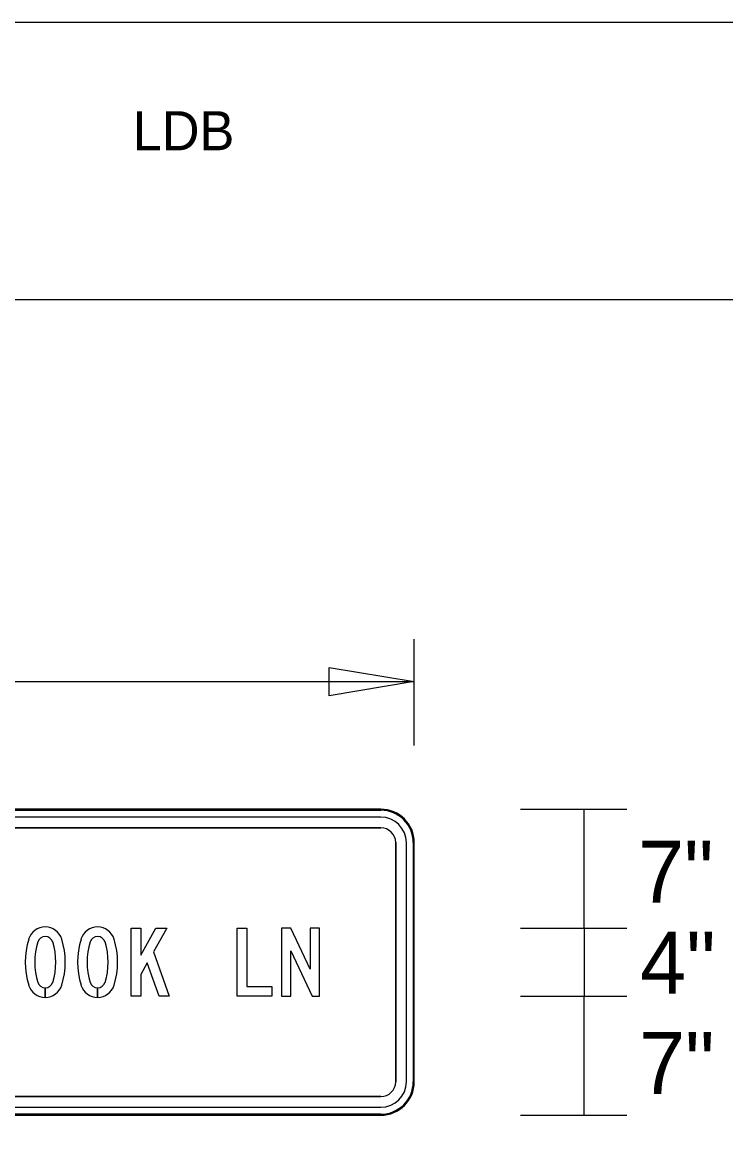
# Model space of a CAD drawing. Extents: x 766449 to 768137, y 650958 to 652521.
# Drawn here: x 767869.7 to 767957.4, y 652115.6 to 652254.2 of the extents above; entities that cross this region are included whole.
import ezdxf

# ---------------------------------------------------------------- set-up
doc = ezdxf.new("R2010")
doc.units = 0
doc.layers.add('Default', color=7, linetype='Continuous')
doc.layers.add('Text', color=7, linetype='Continuous')

msp = doc.modelspace()

# ---------------------------------------------------------------- linework, layer by layer
at = {"layer": 'Default'}
for p, q in [((767918.56, 652164.2), (767918.56, 652177.43)), ((767804.24, 652172.14), (767918.56, 652172.14)), ((767918.56, 652164.2), (767918.56, 652164.2)), ((767914.39, 652156.26), (767808.41, 652156.26)), ((767914.39, 652156.26), (767808.41, 652156.26)), ((767914.39, 652156.26), (767808.41, 652156.26)), ((767914.39, 652156.26), (767808.41, 652156.26)), ((767808.41, 652156.13), (767914.39, 652156.13)), ((767931.79, 652156.26), (767945.02, 652156.26)), ((767931.79, 652156.26), (767931.79, 652156.26)), ((767939.73, 652141.44), (767939.73, 652156.26)), ((767914.39, 652155.27), (767808.41, 652155.27)), ((767914.39, 652155.27), (767808.41, 652155.27)), ((767914.39, 652155.27), (767808.41, 652155.27)), ((767914.39, 652153.95), (767808.41, 652153.95)), ((767808.41, 652153.95), (767914.39, 652153.95)), ((767808.41, 652153.95), (767914.39, 652153.95)), ((767916.24, 652122.32), (767916.24, 652152.09)), ((767916.24, 652152.09), (767916.24, 652122.32)), ((767916.24, 652152.09), (767916.24, 652122.32)), ((767917.57, 652122.32), (767917.57, 652152.09)), ((767917.57, 652122.32), (767917.57, 652152.09)), ((767917.57, 652122.32), (767917.57, 652152.09)), ((767918.43, 652152.09), (767918.43, 652122.32)), ((767918.56, 652122.32), (767918.56, 652152.09)), ((767918.56, 652122.32), (767918.56, 652152.09)), ((767918.56, 652122.32), (767918.56, 652152.09)), ((767918.56, 652122.32), (767918.56, 652152.09)), ((767931.79, 652141.44), (767945.02, 652141.44)), ((767931.79, 652141.44), (767945.02, 652141.44)), ((767939.73, 652141.44), (767939.73, 652132.98)), ((767872.58, 652134.01), (767872.58, 652132.83)), ((767872.58, 652132.83), (767872.58, 652134.01)), ((767872.58, 652134.01), (767872.58, 652132.83)), ((767872.58, 652132.83), (767872.58, 652134.01)), ((767879.1, 652134.01), (767879.1, 652132.83)), ((767879.1, 652132.83), (767879.1, 652134.01)), ((767879.1, 652134.01), (767879.1, 652132.83)), ((767879.1, 652132.83), (767879.1, 652134.01)), ((767931.79, 652132.98), (767945.02, 652132.98)), ((767931.79, 652132.98), (767945.02, 652132.98)), ((767939.73, 652118.16), (767939.73, 652132.98)), ((767808.41, 652120.47), (767914.39, 652120.47)), ((767914.39, 652120.47), (767808.42, 652120.47)), ((767914.39, 652120.47), (767808.42, 652120.47)), ((767808.41, 652119.15), (767914.39, 652119.15)), ((767914.39, 652118.29), (767808.41, 652118.29)), ((767808.41, 652118.16), (767914.39, 652118.16)), ((767808.41, 652118.16), (767914.39, 652118.16)), ((767808.41, 652118.16), (767914.39, 652118.16)), ((767808.41, 652118.16), (767914.39, 652118.16)), ((767808.42, 652119.15), (767914.39, 652119.15)), ((767808.42, 652119.15), (767914.39, 652119.15)), ((767931.79, 652118.16), (767945.02, 652118.16)), ((767931.79, 652118.16), (767931.79, 652118.16))]:
    msp.add_line(p, q, dxfattribs=at)
for points in [[(767918.56, 652172.14), (767907.97, 652170.38), (767907.97, 652173.91)], [(767885.29, 652137.12), (767884.48, 652135.69), (767884.48, 652132.98), (767883.3, 652132.98), (767883.3, 652141.44), (767884.48, 652141.44), (767884.48, 652138.09), (767886.38, 652141.44), (767887.74, 652141.44), (767886.06, 652138.48), (767888.04, 652132.98), (767886.78, 652132.98)], [(767885.29, 652137.12), (767884.48, 652135.69), (767884.48, 652132.98), (767883.3, 652132.98), (767883.3, 652141.44), (767884.48, 652141.44), (767884.48, 652138.09), (767886.38, 652141.44), (767887.74, 652141.44), (767886.06, 652138.48), (767888.04, 652132.98), (767886.78, 652132.98)], [(767885.29, 652137.12), (767884.48, 652135.69), (767884.48, 652132.98), (767883.3, 652132.98), (767883.3, 652141.44), (767884.48, 652141.44), (767884.48, 652138.09), (767886.38, 652141.44), (767887.74, 652141.44), (767886.06, 652138.48), (767888.04, 652132.98), (767886.78, 652132.98)], [(767896.51, 652141.44), (767897.69, 652141.44), (767897.69, 652134.16), (767900.83, 652134.16), (767900.83, 652132.98), (767896.51, 652132.98)], [(767896.51, 652141.44), (767897.69, 652141.44), (767897.69, 652134.16), (767900.83, 652134.16), (767900.83, 652132.98), (767896.51, 652132.98)], [(767896.51, 652141.44), (767897.69, 652141.44), (767897.69, 652134.16), (767900.83, 652134.16), (767900.83, 652132.98), (767896.51, 652132.98)], [(767905.82, 652132.98), (767906.75, 652132.98), (767906.75, 652141.44), (767905.57, 652141.44), (767905.57, 652136.33), (767903.18, 652141.44), (767902.01, 652141.44), (767902.01, 652132.98), (767903.2, 652132.98), (767903.2, 652138.61)], [(767905.82, 652132.98), (767906.75, 652132.98), (767906.75, 652141.44), (767905.57, 652141.44), (767905.57, 652136.33), (767903.18, 652141.44), (767902.01, 652141.44), (767902.01, 652132.98), (767903.2, 652132.98), (767903.2, 652138.61)], [(767905.82, 652132.98), (767906.75, 652132.98), (767906.75, 652141.44), (767905.57, 652141.44), (767905.57, 652136.33), (767903.18, 652141.44), (767902.01, 652141.44), (767902.01, 652132.98), (767903.2, 652132.98), (767903.2, 652138.61)]]:
    msp.add_lwpolyline(points, close=True, dxfattribs=at)
for centre, radius, start, end in [((767914.39, 652152.09), 4.17, 0, 90), ((767914.39, 652152.09), 4.17, 0, 90), ((767914.39, 652152.09), 4.17, 0, 90), ((767914.39, 652152.09), 4.17, 0, 90), ((767914.39, 652152.09), 4.04, 0, 90), ((767914.39, 652152.09), 3.18, 0, 90), ((767914.39, 652152.09), 3.18, 0, 90), ((767914.39, 652152.09), 3.18, 0, 90), ((767914.39, 652152.09), 1.85, 0, 90), ((767914.39, 652152.09), 1.85, 0, 90), ((767914.39, 652152.09), 1.85, 0, 90), ((767914.39, 652122.32), 4.17, 270, 0), ((767914.39, 652122.32), 3.18, 270, 0), ((767914.39, 652122.32), 1.85, 270, 0), ((767914.39, 652122.32), 3.18, 270, 0), ((767914.39, 652122.32), 1.85, 270, 0), ((767914.39, 652122.32), 3.18, 270, 0), ((767914.39, 652122.32), 1.85, 270, 0), ((767914.39, 652122.32), 4.17, 270, 0), ((767914.39, 652122.32), 4.17, 270, 0), ((767914.39, 652122.32), 4.17, 270, 0), ((767914.39, 652122.32), 4.04, 270, 0)]:
    msp.add_arc(centre, radius, start, end, dxfattribs=at)
for centre, major_axis, ratio, start_param, end_param in [((767872.58, 652139.43), (0, 2.16), 0.999997, 5.014824, 7.551546), ((767872.58, 652139.43), (0, 2.16), 0.999997, 5.014824, 7.551546), ((767872.58, 652139.43), (0, 2.16), 0.999997, 5.014824, 7.551546), ((767879.1, 652139.43), (0, 2.16), 0.999995, 5.014824, 7.551546), ((767879.1, 652139.43), (0, 2.16), 0.999995, 5.014824, 7.551546), ((767879.1, 652139.43), (0, 2.16), 0.999995, 5.014824, 7.551546), ((767872.58, 652139.43), (0, 0.974), 0.999997, 5.014824, 7.551546), ((767872.58, 652139.43), (0, 0.974), 0.999997, 5.014824, 7.551546), ((767872.58, 652139.43), (0, 0.974), 0.999997, 5.014824, 7.551546), ((767879.1, 652139.43), (0, 0.974), 0.999995, 5.014824, 7.551546), ((767879.1, 652139.43), (0, 0.974), 0.999995, 5.014824, 7.551546), ((767879.1, 652139.43), (0, 0.974), 0.999995, 5.014824, 7.551546), ((767879.71, 652137.21), (0, 9.62), 0.999997, 1.268361, 1.873232), ((767879.71, 652137.21), (0, 9.62), 0.999997, 1.268361, 1.873232), ((767879.71, 652137.21), (0, 9.62), 0.999997, 1.268361, 1.873232), ((767879.71, 652137.21), (0, 8.44), 0.999997, 1.268361, 1.873232), ((767879.71, 652137.21), (0, 8.44), 0.999997, 1.268361, 1.873232), ((767879.71, 652137.21), (0, 8.44), 0.999997, 1.268361, 1.873232), ((767865.46, 652137.21), (0, 8.44), 0.999997, 4.409954, 5.014824), ((767865.46, 652137.21), (0, 8.44), 0.999997, 4.409954, 5.014824), ((767865.46, 652137.21), (0, 8.44), 0.999997, 4.409954, 5.014824), ((767865.46, 652137.21), (0, 9.62), 0.999997, 4.409954, 5.014824), ((767865.46, 652137.21), (0, 9.62), 0.999997, 4.409954, 5.014824), ((767865.46, 652137.21), (0, 9.62), 0.999997, 4.409954, 5.014824), ((767886.23, 652137.21), (0, 9.62), 0.999995, 1.268361, 1.873232), ((767886.23, 652137.21), (0, 9.62), 0.999995, 1.268361, 1.873232), ((767886.23, 652137.21), (0, 9.62), 0.999995, 1.268361, 1.873232), ((767886.23, 652137.21), (0, 8.44), 0.999995, 1.268361, 1.873232), ((767886.23, 652137.21), (0, 8.44), 0.999995, 1.268361, 1.873232), ((767886.23, 652137.21), (0, 8.44), 0.999995, 1.268361, 1.873232), ((767871.98, 652137.21), (0, 8.44), 0.999995, 4.409954, 5.014824), ((767871.98, 652137.21), (0, 8.44), 0.999995, 4.409954, 5.014824), ((767871.98, 652137.21), (0, 8.44), 0.999995, 4.409954, 5.014824), ((767871.98, 652137.21), (0, 9.62), 0.999995, 4.409954, 5.014824), ((767871.98, 652137.21), (0, 9.62), 0.999995, 4.409954, 5.014824), ((767871.98, 652137.21), (0, 9.62), 0.999995, 4.409954, 5.014824), ((767872.58, 652134.99), (0, 0.974), 0.999997, 1.873232, 4.409954), ((767872.58, 652134.99), (0, 0.974), 0.999997, 1.873232, 3.141593), ((767872.58, 652134.99), (0, 0.974), 0.999997, 1.873232, 3.141593), ((767872.58, 652134.99), (0, 0.974), 0.999997, 3.142027, 4.409954), ((767872.58, 652134.99), (0, 0.974), 0.999997, 3.142027, 4.409954), ((767879.1, 652134.99), (0, 0.974), 0.999995, 1.873232, 4.409954), ((767879.1, 652134.99), (0, 0.974), 0.999995, 1.873232, 3.141593), ((767879.1, 652134.99), (0, 0.974), 0.999995, 1.873232, 3.141593), ((767879.1, 652134.99), (0, 0.974), 0.999995, 3.142027, 4.409954), ((767879.1, 652134.99), (0, 0.974), 0.999995, 3.142027, 4.409954), ((767872.58, 652134.99), (0, 2.16), 0.999997, 1.873232, 4.409954), ((767872.58, 652134.99), (0, 2.16), 0.999997, 1.873232, 3.141593), ((767872.58, 652134.99), (0, 2.16), 0.999997, 1.873232, 3.141593), ((767872.58, 652134.99), (0, 2.16), 0.999997, 3.141789, 4.409954), ((767872.58, 652134.99), (0, 2.16), 0.999997, 3.141789, 4.409954), ((767879.1, 652134.99), (0, 2.16), 0.999995, 1.873232, 4.409954), ((767879.1, 652134.99), (0, 2.16), 0.999995, 1.873232, 3.141593), ((767879.1, 652134.99), (0, 2.16), 0.999995, 1.873232, 3.141593), ((767879.1, 652134.99), (0, 2.16), 0.999995, 3.141789, 4.409954), ((767879.1, 652134.99), (0, 2.16), 0.999995, 3.141789, 4.409954)]:
    msp.add_ellipse(centre, major_axis=major_axis, ratio=ratio, start_param=start_param, end_param=end_param, dxfattribs=at)
at = {"layer": 'Text'}
msp.add_line((767657.51, 652219.7), (768081.66, 652219.7), dxfattribs=at)
msp.add_lwpolyline([(767381.66, 652254.24), (768081.66, 652254.24), (768081.66, 651768.77), (767381.66, 651768.77)], close=True, dxfattribs=at)

# ---------------------------------------------------------------- texts
at = {"layer": 'Default'}
for p in [(767946.43, 652144.6), (767946.56, 652120.81)]:
    msp.add_text('7"', height=7.717, rotation=360, dxfattribs=at).set_placement(p)
msp.add_text('4"', height=7.717, dxfattribs=at).set_placement((767946.7, 652133.3))
at = {"layer": 'Text'}
msp.add_text('LDB', height=4.865, rotation=360, dxfattribs=at).set_placement((767883.49, 652238.3))

doc.saveas('drawing.dxf')
